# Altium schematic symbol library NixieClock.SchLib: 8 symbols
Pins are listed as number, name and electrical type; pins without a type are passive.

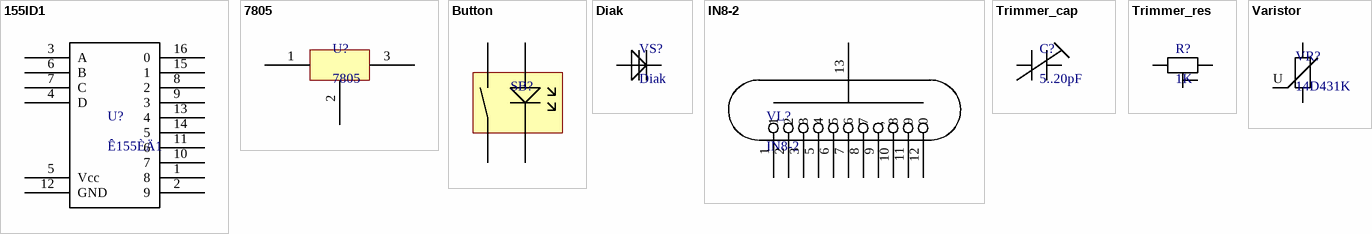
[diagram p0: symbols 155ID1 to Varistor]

## 155ID1
designator U?, comment Ê155ÈÄ1
pins: 1 8, 2 9, 3 A, 4 D, 5 Vcc, 6 B, 7 C, 8 2, 9 3, 10 7, 11 6, 12 GND, 13 4, 14 5, 15 1, 16 0

## 7805
designator U?
pins: 1 In, 2 GND, 3 Out

## Button
designator SB?  (value not drawn)
pins: 1, 2, 3, 4

## Diak
designator VS?
pins: 1, 2

## IN8-2
designator VL?
pins: 1, 2, 3, 5 4, 6 5, 7 6, 8 7, 9 ,, 10 8, 11 9, 12 0, 13

## Trimmer_cap
designator C?, comment 5..20pF
pins: 1, 2

## Trimmer_res
designator R?, comment 1K
pins: 1, 2, 3

## Varistor
designator VR?, comment 14D431K
pins: 1, 2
